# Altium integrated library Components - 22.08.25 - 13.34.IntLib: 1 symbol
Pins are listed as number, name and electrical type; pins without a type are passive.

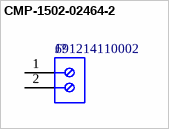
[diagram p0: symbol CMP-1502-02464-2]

## CMP-1502-02464-2
designator J?, comment 691214110002
NexarPartId: 18818288; Plating: Brass, Steel; Current: 10A; Pitch: 3.5052mm; Number of Levels: 1; Number of Contacts: 2; Wire Gauge (Min): 16AWG; Voltage: 300V; Wire Gauge (Max): 24AWG; Stripping Length: -6mm
footprint 691214110002 (3.50 mm Horizontal Entry Modular, 2p)
pins: 1, 2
